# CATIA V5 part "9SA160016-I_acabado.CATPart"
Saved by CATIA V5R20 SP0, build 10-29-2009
Part number: 9SA160016-I_acabado
Revision: ANY
Definition: UNKNOWN
Nomenclature: 9SA160016-I_acabado
Source: Unknown
Bounding box of the stored display mesh (mm): x -4.95 to 4.95, y -14 to 3, z -4.95 to 4.95
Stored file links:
  C:\Users\Utente\Desktop\IO LAVORO\3D X SITO CF\CUMSA\3D files SA\SA 160016\9SA160016-I_acabado.CATPart
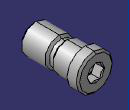
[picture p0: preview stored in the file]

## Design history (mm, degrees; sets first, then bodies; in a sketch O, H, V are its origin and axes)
Body1 "Cortar-Extruir1" (main body)
  Solid1: solid without history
